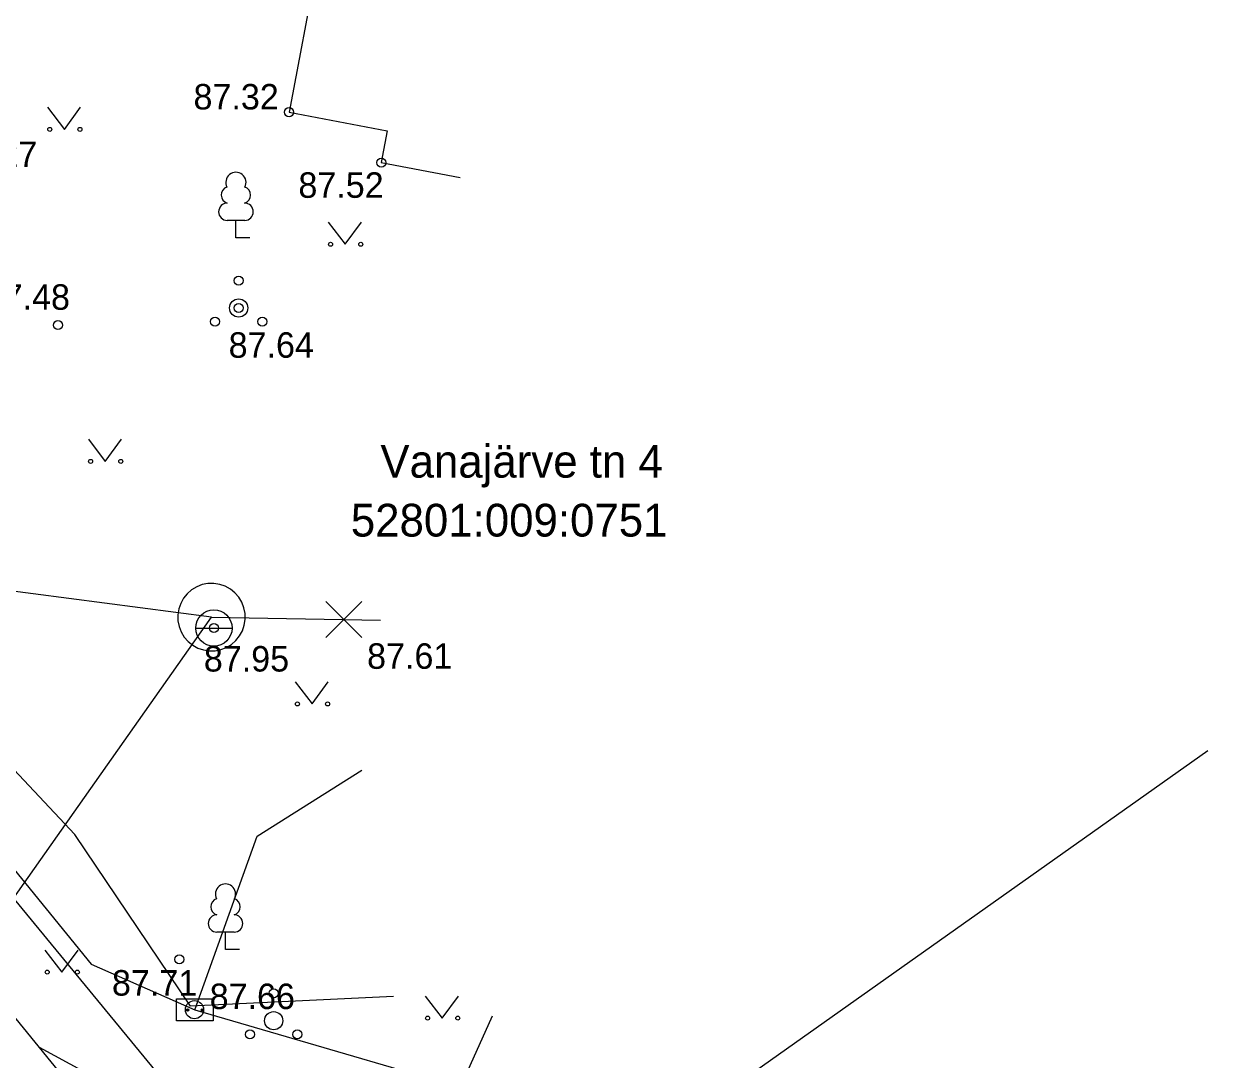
# Model space of a CAD drawing. Extents: x 648748 to 649126, y 6457789 to 6458252.
# Drawn here: x 648976.94 to 649010.23, y 6458052.54 to 6458080.98 of the extents above; entities that cross this region are included whole.
import ezdxf

# ---------------------------------------------------------------- set-up
doc = ezdxf.new("R2010")
doc.units = 0
for name, color, linetype in [('HALJASTUS', 7, 'Continuous'), ('HOONE', 7, 'Continuous'), ('KORGUS-EH2000', 7, 'Continuous'), ('PIIR', 7, 'Continuous'), ('POST', 7, 'Continuous'), ('PUU', 7, 'Continuous'), ('SIOHULIIN', 7, 'Continuous'), ('SIRAJATIS', 7, 'Continuous'), ('SITRASS', 7, 'Continuous'), ('TEE', 7, 'Continuous'), ('VKAEV', 7, 'Continuous'), ('VTRASS', 7, 'Continuous')]:
    doc.layers.add(name, color=color, linetype=linetype)

msp = doc.modelspace()

# ---------------------------------------------------------------- linework, layer by layer
at = {"layer": 'HALJASTUS'}
for p, q in [((648977.58, 6458078.696), (648978.043, 6458078.089)), ((648978.043, 6458078.089), (648978.489, 6458078.696)), ((648985.295, 6458075.54), (648985.758, 6458074.933)), ((648985.758, 6458074.933), (648986.204, 6458075.54)), ((648978.702, 6458069.578), (648979.165, 6458068.971)), ((648979.165, 6458068.971), (648979.611, 6458069.578)), ((648984.383, 6458062.915), (648984.847, 6458062.308)), ((648984.847, 6458062.308), (648985.292, 6458062.915)), ((648977.509, 6458055.55), (648977.973, 6458054.944)), ((648977.973, 6458054.944), (648978.418, 6458055.55)), ((648987.96, 6458054.288), (648988.424, 6458053.681)), ((648988.424, 6458053.681), (648988.869, 6458054.288))]:
    msp.add_line(p, q, dxfattribs=at)
msp.add_lwpolyline([(648987.087, 6458054.275), (648981.505, 6458054.013), (648978.333, 6458058.723), (648973.154, 6458064.224)], dxfattribs=at)
for centre in [(648977.642, 6458078.089), (648978.471, 6458078.089), (648985.357, 6458074.933), (648986.186, 6458074.933), (648978.764, 6458068.971), (648979.593, 6458068.971), (648984.446, 6458062.308), (648985.275, 6458062.308), (648977.572, 6458054.944), (648978.401, 6458054.944), (648988.023, 6458053.681), (648988.852, 6458053.681)]:
    msp.add_circle(centre, 0.055, dxfattribs=at)
at = {"layer": 'HOONE'}
msp.add_lwpolyline([(648990.937, 6458094.909), (648990.022, 6458095.086), (648989.853, 6458094.19), (648987.264, 6458094.679), (648984.216, 6458078.561), (648986.916, 6458078.05), (648986.751, 6458077.176), (648988.913, 6458076.768)], dxfattribs=at)
at = {"layer": 'KORGUS-EH2000'}
for centre in [(648984.216, 6458078.561), (648986.751, 6458077.176), (648982.832, 6458073.184), (648977.865, 6458072.713), (648982.151, 6458064.393), (648981.201, 6458055.293)]:
    msp.add_circle(centre, 0.125, dxfattribs=at)
at = {"layer": 'PIIR'}
for q in [(649009.459, 6458061.03), (648973.89, 6458060.32)]:
    msp.add_line((648986.62, 6458044.87), q, dxfattribs=at)
at = {"layer": 'POST'}
msp.add_circle((648981.617, 6458053.911), 0.25, dxfattribs=at)
at = {"layer": 'PUU'}
for p, q in [((648982.997, 6458075.587), (648982.517, 6458075.587)), ((648982.757, 6458075.112), (648982.757, 6458075.587)), ((648983.137, 6458075.112), (648982.757, 6458075.112)), ((648982.71, 6458056.043), (648982.23, 6458056.043)), ((648982.47, 6458055.567), (648982.47, 6458056.043)), ((648982.85, 6458055.567), (648982.47, 6458055.567))]:
    msp.add_line(p, q, dxfattribs=at)
for centre, radius in [((648982.832, 6458073.934), 0.125), ((648982.832, 6458073.184), 0.25), ((648982.182, 6458072.809), 0.125), ((648983.482, 6458072.809), 0.125), ((648983.792, 6458054.359), 0.125), ((648983.792, 6458053.609), 0.25), ((648983.142, 6458053.234), 0.125), ((648984.442, 6458053.234), 0.125)]:
    msp.add_circle(centre, radius, dxfattribs=at)
for centre, radius, start, end in [((648982.757, 6458076.632), 0.277, 332.58, 207.42), ((648982.587, 6458076.285), 0.233, 109.022, 253.142), ((648982.927, 6458076.285), 0.233, 286.851, 70.986), ((648982.52, 6458075.825), 0.238, 90.002, 269.395), ((648982.995, 6458075.825), 0.238, 270.605, 89.998), ((648982.47, 6458057.088), 0.277, 332.58, 207.42), ((648982.3, 6458056.74), 0.233, 109.022, 253.142), ((648982.64, 6458056.74), 0.233, 286.851, 70.986), ((648982.233, 6458056.28), 0.238, 90.002, 269.395), ((648982.708, 6458056.28), 0.238, 270.605, 89.998)]:
    msp.add_arc(centre, radius, start, end, dxfattribs=at)
at = {"layer": 'SIOHULIIN'}
msp.add_lwpolyline([(648981.628, 6458053.906), (649010.227, 6458045.558)], dxfattribs=at)
at = {"layer": 'SIRAJATIS'}
msp.add_lwpolyline([(648981.128, 6458054.206), (648982.128, 6458054.206), (648982.128, 6458053.606), (648981.128, 6458053.606)], close=True, dxfattribs=at)
for centre, radius in [((648981.428, 6458053.906), 0.0304), ((648981.428, 6458053.906), 0.029), ((648981.428, 6458053.906), 0.0277), ((648981.428, 6458053.906), 0.0263), ((648981.428, 6458053.906), 0.0249), ((648981.428, 6458053.906), 0.0236), ((648981.428, 6458053.906), 0.0222), ((648981.428, 6458053.906), 0.0209), ((648981.428, 6458053.906), 0.0195), ((648981.428, 6458053.906), 0.0181), ((648981.428, 6458053.906), 0.0168), ((648981.428, 6458053.906), 0.0154), ((648981.428, 6458053.906), 0.014), ((648981.428, 6458053.906), 0.0127), ((648981.428, 6458053.906), 0.0113), ((648981.428, 6458053.906), 0.00996), ((648981.428, 6458053.906), 0.0086), ((648981.428, 6458053.906), 0.00724), ((648981.428, 6458053.906), 0.00587), ((648981.428, 6458053.906), 0.00451), ((648981.428, 6458053.906), 0.00315), ((648981.428, 6458053.906), 0.00179), ((648981.428, 6458053.906), 0.000426), ((648981.828, 6458053.906), 0.0304), ((648981.828, 6458053.906), 0.029), ((648981.828, 6458053.906), 0.0277), ((648981.828, 6458053.906), 0.0263), ((648981.828, 6458053.906), 0.0249), ((648981.828, 6458053.906), 0.0236), ((648981.828, 6458053.906), 0.0222), ((648981.828, 6458053.906), 0.0209), ((648981.828, 6458053.906), 0.0195), ((648981.828, 6458053.906), 0.0181), ((648981.828, 6458053.906), 0.0168), ((648981.828, 6458053.906), 0.0154), ((648981.828, 6458053.906), 0.014), ((648981.828, 6458053.906), 0.0127), ((648981.828, 6458053.906), 0.0113), ((648981.828, 6458053.906), 0.00996), ((648981.828, 6458053.906), 0.0086), ((648981.828, 6458053.906), 0.00724), ((648981.828, 6458053.906), 0.00587), ((648981.828, 6458053.906), 0.00451), ((648981.828, 6458053.906), 0.00315), ((648981.828, 6458053.906), 0.00179), ((648981.828, 6458053.906), 0.000426)]:
    msp.add_circle(centre, radius, dxfattribs=at)
at = {"layer": 'SITRASS'}
msp.add_lwpolyline([(648995.643, 6458121.195), (648984.834, 6458121.422), (648983.821, 6458119.744), (648978.901, 6458111.244), (648976.485, 6458102.526), (648974.256, 6458092.094), (648972.583, 6458080.942), (648971.63, 6458075.06), (648971.122, 6458066.021), (648973.701, 6458061.391), (648978.778, 6458055.16), (648981.628, 6458053.906), (648983.341, 6458058.682), (648986.212, 6458060.495)], dxfattribs=at)
at = {"layer": 'TEE'}
for points in [[(649004.65, 6458042.504), (649002.764, 6458040.8), (649000.886, 6458039.29), (648996.637, 6458043.334), (648995.949, 6458042.696), (649001.007, 6458037.421), (649007.735, 6458029.828), (649001.193, 6458023.903), (648995.967, 6458030.098), (648989.468, 6458038.405), (648983.655, 6458045.376), (648980.163, 6458049.435), (648973.986, 6458057.003), (648970.576, 6458062.405), (648968.747, 6458067.645), (648969.273, 6458073.286), (648971.089, 6458082.764), (648972.682, 6458089.018), (648974.902, 6458101.691), (648976.958, 6458108.444), (648978.301, 6458112.451)], [(648989.795, 6458053.731), (648988.932, 6458051.819), (648986.355, 6458050.114), (648983.579, 6458049.784), (648980.204, 6458051.329), (648977.359, 6458052.87)]]:
    msp.add_lwpolyline(points, dxfattribs=at)
at = {"layer": 'VKAEV'}
msp.add_line((648981.651, 6458064.393), (648982.651, 6458064.393), dxfattribs=at)
msp.add_lwpolyline([(648982.15, 6458065.619), (648981.988, 6458065.616), (648981.83, 6458065.585), (648981.679, 6458065.527), (648981.54, 6458065.443), (648981.418, 6458065.337), (648981.317, 6458065.211), (648981.239, 6458065.07), (648981.186, 6458064.917), (648981.161, 6458064.757), (648981.164, 6458064.595), (648981.195, 6458064.436), (648981.254, 6458064.286), (648981.337, 6458064.147), (648981.443, 6458064.025), (648981.569, 6458063.924), (648981.711, 6458063.845), (648981.864, 6458063.793), (648982.024, 6458063.768), (648982.185, 6458063.771), (648982.344, 6458063.802), (648982.495, 6458063.86), (648982.633, 6458063.944), (648982.755, 6458064.05), (648982.857, 6458064.176), (648982.935, 6458064.318), (648982.987, 6458064.471), (648983.013, 6458064.63), (648983.009, 6458064.792), (648982.978, 6458064.951), (648982.92, 6458065.102), (648982.837, 6458065.24), (648982.73, 6458065.362), (648982.605, 6458065.464), (648982.463, 6458065.542), (648982.31, 6458065.594), (648982.15, 6458065.619)], dxfattribs=at)
msp.add_circle((648982.151, 6458064.393), 0.5, dxfattribs=at)
at = {"layer": 'VTRASS'}
for p, q in [((648982.087, 6458064.694), (648964.936, 6458066.922)), ((648985.225, 6458065.122), (648986.215, 6458064.132)), ((648985.225, 6458064.132), (648986.215, 6458065.122)), ((648982.087, 6458064.694), (648986.73, 6458064.608))]:
    msp.add_line(p, q, dxfattribs=at)
msp.add_lwpolyline([(648954.479, 6458025.55), (648956.102, 6458027.829), (648982.087, 6458064.694)], dxfattribs=at)

# ---------------------------------------------------------------- texts
at = {"layer": 'KORGUS-EH2000'}
for s, p in [('87.32', (648981.591, 6458078.635)), ('87.27', (648974.955, 6458077.054)), ('87.52', (648984.473, 6458076.209)), ('87.48', (648975.854, 6458073.134)), ('87.64', (648982.556, 6458071.817)), ('87.95', (648981.875, 6458063.199)), ('87.61', (648986.36, 6458063.274)), ('87.71', (648979.35, 6458054.299)), ('87.66', (648982.035, 6458053.929))]:
    msp.add_text(s, height=0.7, dxfattribs=at).set_placement(p)
at = {"layer": 'PIIR'}
for s, p in [('Vanajärve tn 4', (648986.725, 6458068.524)), ('52801:009:0751', (648985.913, 6458066.906))]:
    msp.add_text(s, height=0.9, rotation=360, dxfattribs=at).set_placement(p)

doc.saveas('drawing.dxf')
